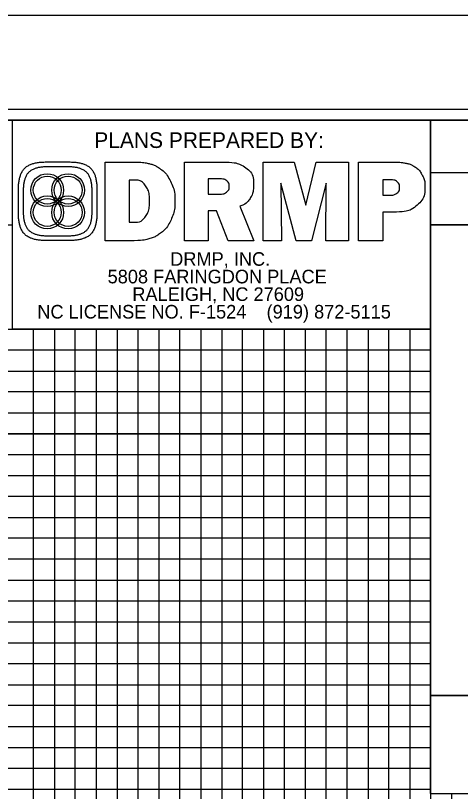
# Model space of a CAD drawing. Extents: x 1262239 to 1263984, y 747221 to 748321.
# Drawn here: x 1263606.4 to 1263712.9, y 748135.2 to 748320.7 of the extents above; entities that cross this region are included whole.
import ezdxf

# ---------------------------------------------------------------- set-up
doc = ezdxf.new("R2010")
doc.units = 0
for name, color, linetype in [('Pattern 1', 7, 'Continuous'), ('Pattern 2', 7, 'Continuous'), ('Prop Drainage Structure Bridge Opening', 7, 'Continuous'), ('Prop Grid Mask', 7, 'Continuous'), ('Prop Horizontal Alignment', 7, 'Continuous'), ('Prop Paved Shoulder', 7, 'Continuous'), ('Prop PFL Text', 7, 'Continuous'), ('Prop Terminator CELL', 7, 'Continuous'), ('Prop VPI Label', 7, 'Continuous'), ('Sheet Block System Information CELL', 7, 'Continuous'), ('Sheet Layout Plan Border', 7, 'Continuous'), ('Sheet Project Info Box CELL', 7, 'Continuous'), ('Sheet Sticker Exception Certification CELL', 7, 'Continuous')]:
    doc.layers.add(name, color=color, linetype=linetype)

msp = doc.modelspace()

# ---------------------------------------------------------------- linework, layer by layer
at = {"layer": 'Pattern 1'}
for points in [[(1263705.7, 748220.74), (1262405.85, 748220.74), (1262405.85, 748270.69), (1263605.75, 748270.69)], [(1263655.75, 748245.74), (1263655.75, 747270.74), (1263705.75, 747270.74), (1263705.75, 748245.74)], [(1263905.75, 748120.74), (1262405.75, 748120.74), (1262405.75, 748170.74), (1263705.7, 748170.74)]]:
    msp.add_lwpolyline(points, dxfattribs=at)
at = {"layer": 'Pattern 2'}
for points in [[(1262405.75, 748245.74), (1263705.7, 748245.74)], [(1263630.75, 748245.74), (1263630.75, 747270.74), (1263680.75, 747270.74), (1263680.75, 748245.74)], [(1263705.7, 748195.74), (1262405.75, 748195.74), (1262405.75, 748145.69), (1263705.7, 748145.69)]]:
    msp.add_lwpolyline(points, dxfattribs=at)
at = {"layer": 'Prop Drainage Structure Bridge Opening'}
msp.add_line((1263922.75, 748320.74), (1262238.75, 748320.74), dxfattribs=at)
at = {"layer": 'Prop Grid Mask'}
msp.add_lwpolyline([(1262455.75, 748295.74), (1263705.7, 748295.74), (1263705.7, 748134.69), (1263855.75, 748134.69), (1263855.75, 747270.74), (1262455.75, 747270.74)], close=True, dxfattribs=at)
at = {"layer": 'Prop Horizontal Alignment'}
msp.add_lwpolyline([(1263705.7, 748295.74), (1263705.7, 748245.74), (1263605.75, 748245.74), (1263605.75, 748295.74)], close=True, dxfattribs=at)
msp.add_lwpolyline([(1263705.7, 748295.74), (1263705.7, 748245.74), (1263605.75, 748245.74), (1263605.75, 748295.74)], close=True, dxfattribs=at)
at = {"layer": 'Prop Paved Shoulder'}
msp.add_line((1263705.7, 748283.19), (1263905.75, 748283.19), dxfattribs=at)
for points in [[(1263905.75, 748295.74), (1262405.75, 748295.74), (1262405.75, 747245.74), (1263905.75, 747245.74)], [(1263705.7, 748295.74), (1263905.75, 748295.74), (1263905.75, 748270.69), (1263705.7, 748270.69)], [(1263705.7, 748270.69), (1263805.75, 748270.69), (1263805.75, 748158.19), (1263705.7, 748158.19)]]:
    msp.add_lwpolyline(points, close=True, dxfattribs=at)
at = {"layer": 'Prop PFL Text'}
for p, q in [((1263655.75, 748245.74), (1263655.75, 747270.74)), ((1262405.75, 748220.74), (1263705.7, 748220.74)), ((1262405.75, 748170.74), (1263705.7, 748170.74)), ((1263705.75, 747270.74), (1263705.75, 748158.19))]:
    msp.add_line(p, q, dxfattribs=at)
at = {"layer": 'Prop Terminator CELL'}
msp.add_lwpolyline([(1263918.25, 748298.29), (1262251.75, 748298.29), (1262251.75, 747243.19), (1263918.25, 747243.19)], close=True, dxfattribs=at)
at = {"layer": 'Prop VPI Label'}
msp.add_lwpolyline([(1263922.75, 748320.74), (1262238.75, 748320.74), (1262238.75, 747220.74), (1263922.75, 747220.74)], close=True, dxfattribs=at)
at = {"layer": 'Sheet Block System Information CELL'}
for centre, radius in [((1263614.03, 748278.99), 3.93), ((1263614.03, 748278.99), 3.34), ((1263619.03, 748278.99), 3.93), ((1263619.03, 748278.99), 3.34), ((1263614.03, 748273.66), 3.93), ((1263614.03, 748273.66), 3.34), ((1263619.03, 748273.66), 3.93), ((1263619.03, 748273.66), 3.34)]:
    msp.add_circle(centre, radius, dxfattribs=at)
at = {"layer": 'Sheet Layout Plan Border'}
for p, q in [((1263705.7, 748134.69), (1263705.7, 748158.19)), ((1263705.7, 748158.19), (1263905.74, 748158.19))]:
    msp.add_line(p, q, dxfattribs=at)
at = {"layer": 'Sheet Project Info Box CELL'}
for p, q in [((1263613.81, 748285.72), (1263619.26, 748285.72)), ((1263665.69, 748266.9), (1263665.69, 748285.7)), ((1263665.69, 748285.7), (1263673.08, 748285.7)), ((1263673.08, 748285.7), (1263675.9, 748275.43)), ((1263675.9, 748275.43), (1263678.38, 748285.7)), ((1263678.38, 748285.7), (1263686.1, 748285.7)), ((1263686.1, 748285.7), (1263686.1, 748266.9)), ((1263618.92, 748284.57), (1263614.14, 748284.57)), ((1263673.54, 748266.9), (1263669.89, 748280.69)), ((1263669.89, 748280.69), (1263670.08, 748266.9)), ((1263680.77, 748280.69), (1263677.19, 748266.9)), ((1263680.68, 748266.9), (1263680.77, 748280.69)), ((1263607.14, 748273.6), (1263607.14, 748279.05)), ((1263608.29, 748278.72), (1263608.29, 748273.94)), ((1263624.77, 748273.94), (1263624.77, 748278.72)), ((1263625.92, 748279.05), (1263625.92, 748273.6)), ((1263619.26, 748266.94), (1263613.81, 748266.94)), ((1263614.14, 748268.08), (1263618.92, 748268.08)), ((1263670.08, 748266.9), (1263665.69, 748266.9)), ((1263677.19, 748266.9), (1263673.54, 748266.9)), ((1263686.1, 748266.9), (1263680.68, 748266.9))]:
    msp.add_line(p, q, dxfattribs=at)
for points in [[(1263634.84, 748266.9), (1263627.86, 748266.9), (1263627.86, 748285.7), (1263635.09, 748285.7)], [(1263660.08, 748275.12), (1263663.47, 748266.9), (1263657.29, 748266.9), (1263654.51, 748274.03), (1263652.54, 748274.03), (1263652.54, 748266.9), (1263646.82, 748266.9), (1263646.82, 748285.7), (1263656, 748285.7)], [(1263697.59, 748273.75), (1263694.25, 748273.75), (1263694.25, 748266.9), (1263688.49, 748266.9), (1263688.49, 748285.7), (1263696.5, 748285.7)], [(1263635.09, 748281.38), (1263633.62, 748281.38), (1263633.62, 748271.3), (1263634.92, 748271.3)], [(1263655.19, 748281.69), (1263652.54, 748281.69), (1263652.54, 748278.01), (1263655.27, 748278.01)], [(1263696.15, 748281.45), (1263694.25, 748281.45), (1263694.25, 748277.76), (1263695.8, 748277.76)]]:
    msp.add_lwpolyline(points, dxfattribs=at)
for points, degree in [([(1263607.14, 748279.05), (1263607.14, 748282.72), (1263610.14, 748285.72), (1263613.81, 748285.72)], 2), ([(1263619.26, 748285.72), (1263622.92, 748285.72), (1263625.92, 748282.72), (1263625.92, 748279.05)], 2), ([(1263635.09, 748285.7), (1263636.23, 748285.7), (1263637.25, 748285.6), (1263638.15, 748285.39), (1263639.05, 748285.19), (1263639.83, 748284.88), (1263640.51, 748284.45), (1263641.79, 748283.64), (1263642.79, 748282.53), (1263643.5, 748281.1), (1263644.21, 748279.68), (1263644.57, 748278.08), (1263644.57, 748276.31), (1263644.57, 748274.74), (1263644.26, 748273.27), (1263643.63, 748271.9), (1263643, 748270.54), (1263642.15, 748269.45), (1263641.07, 748268.64), (1263640.27, 748268.05), (1263639.36, 748267.61), (1263638.35, 748267.33), (1263637.34, 748267.05), (1263636.17, 748266.9), (1263634.84, 748266.9)], 3), ([(1263656, 748285.7), (1263658.46, 748285.7), (1263660.3, 748285.24), (1263661.53, 748284.33), (1263662.75, 748283.42), (1263663.36, 748282.04), (1263663.36, 748280.21), (1263663.36, 748278.94), (1263663.08, 748277.87), (1263662.52, 748276.99), (1263661.96, 748276.12), (1263661.15, 748275.49), (1263660.08, 748275.12)], 3), ([(1263696.5, 748285.7), (1263697.76, 748285.7), (1263698.8, 748285.62), (1263699.62, 748285.47), (1263700.44, 748285.31), (1263701.13, 748285.07), (1263701.68, 748284.73), (1263702.56, 748284.18), (1263703.23, 748283.48), (1263703.68, 748282.63), (1263704.14, 748281.78), (1263704.36, 748280.82), (1263704.36, 748279.74), (1263704.36, 748277.95), (1263703.74, 748276.51), (1263702.5, 748275.41), (1263701.25, 748274.3), (1263699.62, 748273.75), (1263697.59, 748273.75)], 3), ([(1263614.14, 748284.57), (1263610.92, 748284.57), (1263608.29, 748281.93), (1263608.29, 748278.72)], 2), ([(1263624.77, 748278.72), (1263624.77, 748281.93), (1263622.14, 748284.57), (1263618.92, 748284.57)], 2), ([(1263634.92, 748271.3), (1263636, 748271.3), (1263636.86, 748271.76), (1263637.51, 748272.69), (1263638.16, 748273.61), (1263638.49, 748274.85), (1263638.49, 748276.39), (1263638.49, 748277.92), (1263638.18, 748279.13), (1263637.56, 748280.03), (1263636.95, 748280.93), (1263636.13, 748281.38), (1263635.09, 748281.38)], 3), ([(1263655.27, 748278.01), (1263655.94, 748278.01), (1263656.49, 748278.18), (1263656.91, 748278.53), (1263657.33, 748278.87), (1263657.55, 748279.31), (1263657.55, 748279.85), (1263657.55, 748280.47), (1263657.35, 748280.93), (1263656.96, 748281.23), (1263656.57, 748281.53), (1263655.98, 748281.69), (1263655.19, 748281.69)], 3), ([(1263695.8, 748277.76), (1263696.58, 748277.76), (1263697.18, 748277.93), (1263697.62, 748278.25), (1263698.05, 748278.58), (1263698.27, 748279.03), (1263698.27, 748279.61), (1263698.27, 748280.2), (1263698.08, 748280.66), (1263697.72, 748280.98), (1263697.36, 748281.29), (1263696.84, 748281.45), (1263696.15, 748281.45)], 3), ([(1263613.81, 748266.94), (1263610.14, 748266.94), (1263607.14, 748269.94), (1263607.14, 748273.6)], 2), ([(1263608.29, 748273.94), (1263608.29, 748270.72), (1263610.92, 748268.08), (1263614.14, 748268.08)], 2), ([(1263618.92, 748268.08), (1263622.14, 748268.08), (1263624.77, 748270.72), (1263624.77, 748273.94)], 2), ([(1263625.92, 748273.6), (1263625.92, 748269.94), (1263622.92, 748266.94), (1263619.26, 748266.94)], 2)]:
    msp.add_open_spline(points, degree=degree, dxfattribs=at)
at = {"layer": 'Sheet Sticker Exception Certification CELL'}
for points in [[(1263610.75, 747270.74), (1263610.75, 748245.74)], [(1263615.75, 748245.74), (1263615.75, 747270.74), (1263620.75, 747270.74), (1263620.75, 748245.74)], [(1263625.75, 748245.74), (1263625.75, 747270.74), (1263635.75, 747270.74), (1263635.75, 748245.74)], [(1263640.75, 748245.74), (1263640.75, 747270.74), (1263645.75, 747270.74), (1263645.75, 748245.74)], [(1263650.75, 748245.74), (1263650.75, 747270.74), (1263660.75, 747270.74), (1263660.75, 748245.74)], [(1263665.75, 748245.74), (1263665.75, 747270.74), (1263670.75, 747270.74), (1263670.75, 748245.74)], [(1263675.75, 748245.74), (1263675.75, 747270.74), (1263685.75, 747270.74), (1263685.75, 748245.74)], [(1263690.75, 748245.74), (1263690.75, 747270.74), (1263695.75, 747270.74), (1263695.75, 748245.74)], [(1263700.75, 748245.74), (1263700.75, 747270.74), (1263710.75, 747270.74), (1263710.75, 748134.69)], [(1263705.7, 748240.74), (1262455.75, 748240.74), (1262455.75, 748235.74), (1263705.7, 748235.74)], [(1263705.7, 748230.74), (1262455.75, 748230.74), (1262455.75, 748225.74), (1263705.7, 748225.74)], [(1263705.7, 748215.74), (1262455.75, 748215.74), (1262455.75, 748210.74), (1263705.7, 748210.74)], [(1263705.7, 748205.74), (1262455.75, 748205.74), (1262455.75, 748200.74), (1263705.7, 748200.74)], [(1263705.7, 748190.74), (1262455.75, 748190.74), (1262455.75, 748185.74), (1263705.7, 748185.74)], [(1263705.7, 748180.74), (1262455.75, 748180.74), (1262455.75, 748175.74), (1263705.7, 748175.74)], [(1263705.7, 748165.74), (1262455.75, 748165.74), (1262455.75, 748160.74), (1263705.7, 748160.74)], [(1263705.7, 748155.74), (1262455.75, 748155.74), (1262455.75, 748155.74), (1262455.75, 748135.74), (1263705.7, 748135.74)], [(1262455.75, 748150.74), (1263705.7, 748150.74)], [(1263705.7, 748140.74), (1262455.75, 748140.74)]]:
    msp.add_lwpolyline(points, dxfattribs=at)

# ---------------------------------------------------------------- texts
at = {"layer": 'Sheet Block System Information CELL'}
msp.add_text('PLANS PREPARED BY:', height=3.75, rotation=360, dxfattribs=at).set_placement((1263625.28, 748289.07))
for s, p in [('DRMP, INC.', (1263643.44, 748260.9)), ('5808 FARINGDON PLACE', (1263628.47, 748256.7)), ('RALEIGH, NC 27609', (1263634.38, 748252.49)), ('NC LICENSE NO. F-1524    (919) 872-5115', (1263611.66, 748248.29))]:
    msp.add_text(s, height=3.25, dxfattribs=at).set_placement(p)

doc.saveas('drawing.dxf')
